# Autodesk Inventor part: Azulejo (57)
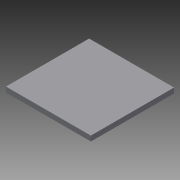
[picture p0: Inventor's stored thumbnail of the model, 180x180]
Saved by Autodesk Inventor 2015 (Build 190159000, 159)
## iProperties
Created: 2015-04
Part Number: Azulejo (57)
Material: Genérico
Document SubType Name: Modeling
Designer: Felipe
Density: 1 g/cm^3
Appearance: Padrão
Author: Felipe
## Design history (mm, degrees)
sketch "Sketch1"
  geometry: L1 (-5999.978, 1162.687)-(-5915.126, 1162.687); L2 (6980.022, 1162.687)-(6895.169, 1162.687); L3 (-1034.12, -6357.313)-(-1063.775, -6417.313); L4 (-5519.978, 1582.687)-(-6306.841, 1582.687); L5 (5000.022, -4857.313)-(6000.022, -4857.313); L6 (6000.022, -4857.313)-(6000.022, -6277.313); L7 (6000.022, -4837.313)-(5000.022, -4837.313); L8 (5000.022, -4837.313)-(5000.022, -3357.313); L9 (5000.022, -3357.313)-(6000.022, -3357.313); L10 (6000.022, -3357.313)-(6000.022, -4837.313); L11 (6000.022, -3337.313)-(5000.022, -3337.313); L12 (5000.022, -3337.313)-(5000.022, -1857.313); L13 (5000.022, -1857.313)-(6000.022, -1857.313); L14 (6000.022, -1857.313)-(6000.022, -3337.313); L15 (6000.022, -1837.313)-(5000.022, -1837.313); L16 (5000.022, -1837.313)-(5000.022, -357.313); L17 (5000.022, -357.313)-(6000.022, -357.313); L18 (6000.022, -357.313)-(6000.022, -1837.313); L19 (4000.022, -4837.313)-(3500.022, -4837.313); L20 (3500.022, -4837.313)-(3500.022, -3357.313); L21 (3500.022, -3357.313)-(4000.022, -3357.313); L22 (4000.022, -3357.313)-(4000.022, -4837.313); L23 (4000.022, -3337.313)-(3500.022, -3337.313); L24 (3500.022, -3337.313)-(3500.022, -1857.313); L25 (2000.022, 2662.687)-(2480.022, 2662.687); L26 (500.022, 2662.687)-(1980.022, 2662.687); L27 (-999.978, 2662.687)-(480.022, 2662.687); L28 (3500.022, -1857.313)-(4000.022, -1857.313); L29 (4000.022, -1857.313)-(4000.022, -3337.313); L30 (4000.022, -1837.313)-(3500.022, -1837.313); L31 (3500.022, -1837.313)-(3500.022, -357.313); L32 (3500.022, -357.313)-(4000.022, -357.313); L33 (4000.022, -357.313)-(4000.022, -1837.313); L34 (-5519.978, 1142.687)-(-5519.978, -337.313); L35 (6500.022, -337.313)-(6500.022, 1142.687); L36 (6480.022, 2662.687)-(5000.022, 2662.687); L37 (5000.022, 2642.687)-(6480.022, 2642.687); L38 (6480.022, 1142.687)-(6480.022, -337.313); L39 (6480.022, -337.313)-(5000.022, -337.313); L40 (5000.022, -337.313)-(5000.022, 1142.687); L41 (7965.922, 2662.687)-(6500.022, 2662.687); L42 (6500.022, 2642.687)-(7965.922, 2642.687); L43 (4980.022, 2662.687)-(3500.022, 2662.687); L44 (3500.022, 2642.687)-(4980.022, 2642.687); L45 (4980.022, 1142.687)-(4980.022, -337.313); L46 (4980.022, -337.313)-(3500.022, -337.313); L47 (3500.022, -337.313)-(3500.022, 1142.687); L48 (3500.022, -1837.313)-(3500.022, -357.313); L49 (3500.022, -3337.313)-(3500.022, -1857.313); L50 (3500.022, -4837.313)-(3500.022, -3357.313); L51 (3500.022, -6257.313)-(3500.022, -4857.313); L52 (4000.022, -6277.313)-(3500.022, -6277.313); L53 (3500.022, -6277.313)-(3500.022, -4857.313); L54 (3480.022, 1162.687)-(2000.022, 1162.687); L55 (2000.022, 1142.687)-(3480.022, 1142.687); L56 (3480.022, 1142.687)-(3480.022, -337.313); L57 (3480.022, -337.313)-(2000.022, -337.313); L58 (2000.022, -337.313)-(2000.022, 1142.687); L59 (3480.022, -357.313)-(3480.022, -1837.313); L60 (3480.022, -1857.313)-(3480.022, -3337.313); L61 (3480.022, -3357.313)-(3480.022, -4837.313); L62 (3480.022, -4857.313)-(3480.022, -6277.313); L63 (3500.022, -4857.313)-(4000.022, -4857.313); L64 (1980.022, 1162.687)-(500.022, 1162.687)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; 5 further points
  constraints: 1802 end point, 96 point on line, 2 other
extrude "Extrusion1" new body sketch "Sketch1" distance "d0" = 60; taper "d1" = 0 deg
body "Solid1"
